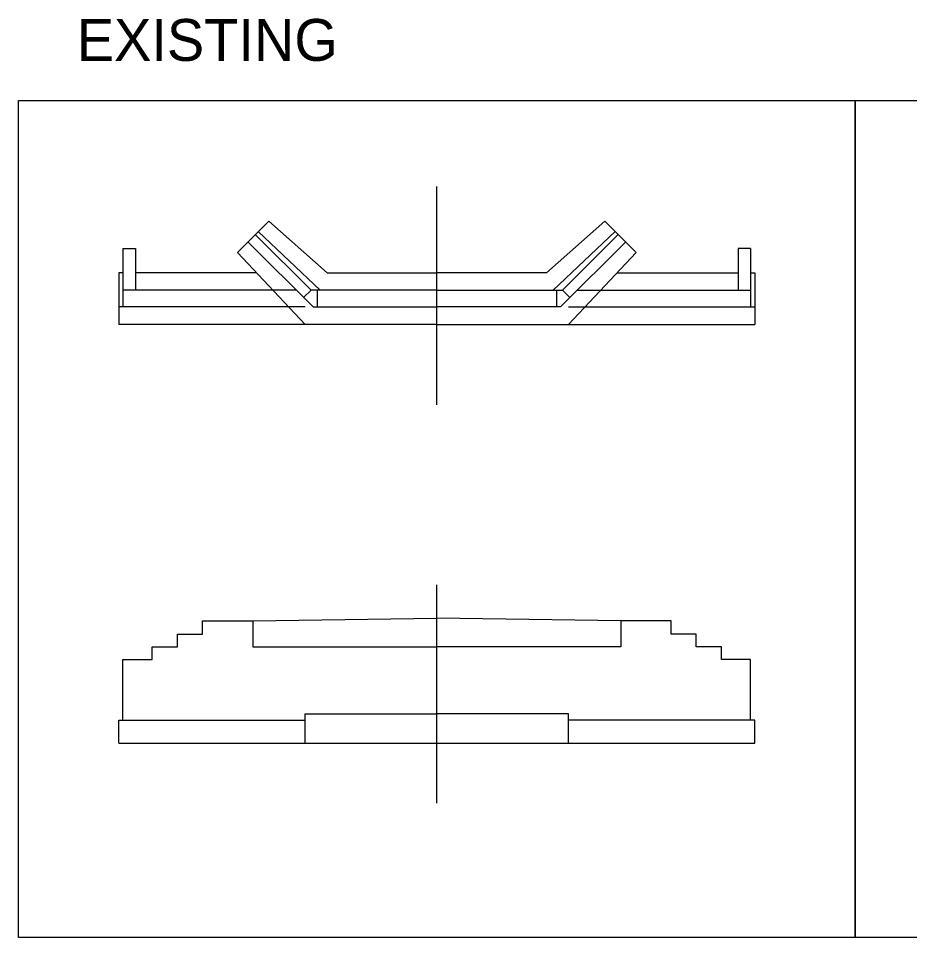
# Model space of a CAD drawing. Extents: x 1546689 to 1550004, y 741079 to 745265.
# Drawn here: x 1546913.9 to 1547020.4, y 744017.2 to 744127 of the extents above; entities that cross this region are included whole.
import ezdxf

# ---------------------------------------------------------------- set-up
doc = ezdxf.new("R2010")
doc.units = 0
for name, color, linetype in [('BR_X_Rail_Object', 7, 'Continuous'), ('Level 41', 7, 'Continuous'), ('Level 42', 7, 'Continuous'), ('Wetland', 7, 'Continuous')]:
    doc.layers.add(name, color=color, linetype=linetype)

msp = doc.modelspace()

# ---------------------------------------------------------------- linework, layer by layer
at = {"layer": 'BR_X_Rail_Object'}
for p, q in [((1546963.88, 744080.81), (1546963.88, 744106.89)), ((1546963.88, 744033.25), (1546963.88, 744059.32))]:
    msp.add_line(p, q, dxfattribs=at)
at = {"layer": 'Level 41'}
for points in [[(1546913.88, 744117.18), (1547013.88, 744117.18), (1547013.88, 744017.18), (1546913.88, 744017.18)], [(1547013.88, 744117.18), (1547213.88, 744117.18), (1547213.88, 744017.18), (1547013.88, 744017.18)]]:
    msp.add_lwpolyline(points, close=True, dxfattribs=at)
at = {"layer": 'Level 42'}
for p, q in [((1546941.88, 744055.01), (1546963.88, 744055.35)), ((1546941.88, 744055.01), (1546941.88, 744051.92)), ((1546985.88, 744055.01), (1546963.88, 744055.35)), ((1546985.88, 744055.01), (1546985.88, 744051.92)), ((1546941.88, 744051.92), (1546963.88, 744051.92)), ((1546985.88, 744051.92), (1546963.88, 744051.92))]:
    msp.add_line(p, q, dxfattribs=at)
at = {"layer": 'Wetland'}
for p, q in [((1546940.06, 744099.03), (1546943.8, 744102.77)), ((1546943.8, 744102.77), (1546950.78, 744096.59)), ((1546983.96, 744102.77), (1546976.98, 744096.59)), ((1546987.7, 744099.03), (1546983.96, 744102.77)), ((1546948.85, 744094.51), (1546942.19, 744101.17)), ((1546949.96, 744094.51), (1546942.55, 744101.52)), ((1546977.8, 744094.51), (1546985.21, 744101.52)), ((1546978.91, 744094.51), (1546985.57, 744101.17)), ((1546949.09, 744092.51), (1546941.31, 744100.28)), ((1546978.67, 744092.51), (1546986.45, 744100.28)), ((1546926.38, 744099.51), (1546926.38, 744092.51)), ((1546926.38, 744099.51), (1546927.88, 744099.51)), ((1546927.88, 744099.51), (1546927.88, 744094.51)), ((1546940.06, 744099.03), (1546948.13, 744090.42)), ((1546987.7, 744099.03), (1546979.63, 744090.42)), ((1546999.88, 744099.51), (1546999.88, 744094.51)), ((1547001.38, 744099.51), (1546999.88, 744099.51)), ((1547001.38, 744099.51), (1547001.38, 744092.51)), ((1546925.88, 744096.59), (1546925.88, 744090.42)), ((1546926.38, 744096.59), (1546925.88, 744096.59)), ((1546942.35, 744096.59), (1546927.88, 744096.59)), ((1546950.78, 744096.59), (1546963.88, 744096.59)), ((1546976.98, 744096.59), (1546963.88, 744096.59)), ((1546985.41, 744096.59), (1546999.88, 744096.59)), ((1547001.38, 744096.59), (1547001.88, 744096.59)), ((1547001.88, 744096.59), (1547001.88, 744090.42)), ((1546947.09, 744094.51), (1546926.38, 744094.51)), ((1546947.97, 744093.63), (1546948.85, 744094.51)), ((1546963.88, 744094.51), (1546948.85, 744094.51)), ((1546949.59, 744094.51), (1546949.59, 744092.51)), ((1546963.88, 744094.51), (1546978.91, 744094.51)), ((1546978.17, 744094.51), (1546978.17, 744092.51)), ((1546979.79, 744093.63), (1546978.91, 744094.51)), ((1546980.67, 744094.51), (1547001.38, 744094.51)), ((1546948.13, 744092.51), (1546925.88, 744092.51)), ((1546949.09, 744092.51), (1546963.88, 744092.51)), ((1546978.67, 744092.51), (1546963.88, 744092.51)), ((1546979.63, 744092.51), (1547001.88, 744092.51)), ((1546948.13, 744090.42), (1546925.88, 744090.42)), ((1546963.88, 744090.42), (1546948.13, 744090.42)), ((1546963.88, 744090.42), (1546979.63, 744090.42)), ((1546979.63, 744090.42), (1547001.88, 744090.42)), ((1546935.88, 744053.42), (1546935.88, 744055.01)), ((1546935.88, 744055.01), (1546941.88, 744055.01)), ((1546991.88, 744055.01), (1546985.88, 744055.01)), ((1546991.88, 744053.42), (1546991.88, 744055.01)), ((1546932.88, 744051.92), (1546932.88, 744053.42)), ((1546932.88, 744053.42), (1546935.88, 744053.42)), ((1546994.88, 744053.42), (1546991.88, 744053.42)), ((1546994.88, 744051.92), (1546994.88, 744053.42)), ((1546929.88, 744050.42), (1546929.88, 744051.92)), ((1546929.88, 744051.92), (1546932.88, 744051.92)), ((1546997.88, 744051.92), (1546994.88, 744051.92)), ((1546997.88, 744050.42), (1546997.88, 744051.92)), ((1546926.38, 744043.17), (1546926.38, 744050.42)), ((1546926.38, 744050.42), (1546929.88, 744050.42)), ((1547001.38, 744050.42), (1546997.88, 744050.42)), ((1547001.38, 744043.17), (1547001.38, 744050.42)), ((1546948.13, 744043.92), (1546963.88, 744043.92)), ((1546948.13, 744040.42), (1546948.13, 744043.92)), ((1546979.63, 744043.92), (1546963.88, 744043.92)), ((1546979.63, 744040.42), (1546979.63, 744043.92)), ((1546925.88, 744040.42), (1546925.88, 744043.17)), ((1546925.88, 744043.17), (1546948.13, 744043.17)), ((1547001.88, 744043.17), (1546979.63, 744043.17)), ((1547001.88, 744040.42), (1547001.88, 744043.17)), ((1546925.88, 744040.42), (1547001.88, 744040.42))]:
    msp.add_line(p, q, dxfattribs=at)

# ---------------------------------------------------------------- texts
at = {"layer": 'Level 41'}
msp.add_text('EXISTING', height=5, dxfattribs=at).set_placement((1546920.85, 744121.91))

doc.saveas('drawing.dxf')
